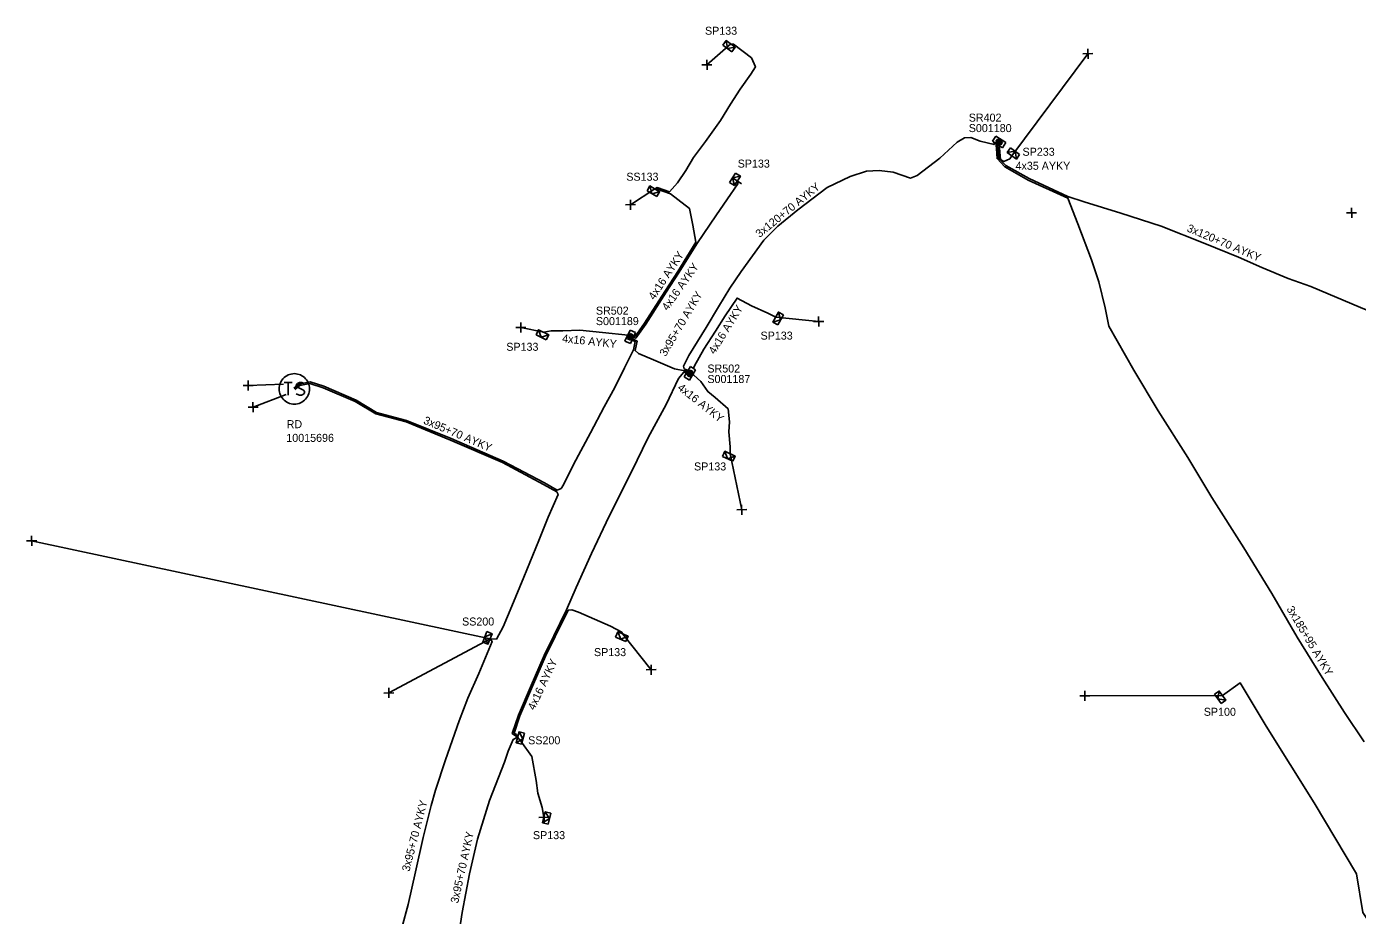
# Model space of a CAD drawing. Extents: x -762504 to -761250, y -1152974 to -1152253.
# Drawn here: x -761820.6 to -761655.3, y -1152363.5 to -1152253.1 of the extents above; entities that cross this region are included whole.
import ezdxf

# ---------------------------------------------------------------- set-up
doc = ezdxf.new("R2010")
doc.units = 0
for name, color, linetype in [('Vrstva 25', 7, 'Continuous'), ('Vrstva 26', 7, 'Continuous'), ('Vrstva 27', 7, 'Continuous'), ('Vrstva 28', 7, 'Continuous'), ('Vrstva 29', 7, 'Continuous'), ('Vrstva 30', 7, 'Continuous'), ('Vrstva 31', 7, 'Continuous'), ('Vrstva 33', 7, 'Continuous'), ('Vrstva 34', 7, 'Continuous'), ('Vrstva 5', 7, 'Continuous'), ('Vrstva 52', 7, 'Continuous'), ('Vrstva 54', 7, 'Continuous'), ('Vrstva 59', 7, 'Continuous'), ('Vrstva 6', 7, 'Continuous')]:
    doc.layers.add(name, color=color, linetype=linetype)

msp = doc.modelspace()

# ---------------------------------------------------------------- linework, layer by layer
at = {"layer": 'Vrstva 25'}
for points in [[(-761785.487, -1152298.121), (-761785.498, -1152297.924), (-761785.529, -1152297.728), (-761785.58, -1152297.537), (-761785.651, -1152297.352), (-761785.741, -1152297.177), (-761785.849, -1152297.011), (-761785.973, -1152296.857), (-761786.113, -1152296.717), (-761786.267, -1152296.593), (-761786.433, -1152296.485), (-761786.609, -1152296.395), (-761786.793, -1152296.324), (-761787.18, -1152296.242), (-761787.18, -1152296.242), (-761787.377, -1152296.231), (-761787.575, -1152296.242), (-761787.771, -1152296.273), (-761787.961, -1152296.324), (-761788.147, -1152296.395), (-761788.322, -1152296.485), (-761788.488, -1152296.593), (-761788.642, -1152296.717), (-761788.782, -1152296.857), (-761788.906, -1152297.011), (-761789.014, -1152297.177), (-761789.104, -1152297.352), (-761789.175, -1152297.537), (-761789.226, -1152297.728), (-761789.257, -1152297.924), (-761789.268, -1152298.121), (-761789.257, -1152298.319), (-761789.226, -1152298.515), (-761789.175, -1152298.705), (-761789.104, -1152298.89), (-761789.014, -1152299.066), (-761788.906, -1152299.232), (-761788.781, -1152299.386), (-761788.642, -1152299.525), (-761788.488, -1152299.65), (-761788.322, -1152299.758), (-761788.146, -1152299.848), (-761787.961, -1152299.919), (-761787.771, -1152299.97), (-761787.575, -1152300.001), (-761787.377, -1152300.012), (-761787.18, -1152300.001), (-761786.984, -1152299.97), (-761786.793, -1152299.919), (-761786.609, -1152299.848), (-761786.433, -1152299.758), (-761786.267, -1152299.65), (-761786.113, -1152299.525), (-761785.973, -1152299.386), (-761785.849, -1152299.232), (-761785.741, -1152299.066), (-761785.651, -1152298.89), (-761785.58, -1152298.705), (-761785.529, -1152298.515), (-761785.498, -1152298.319), (-761785.487, -1152298.121)], [(-761788.639, -1152297.338), (-761787.631, -1152297.338)], [(-761788.135, -1152297.338), (-761788.135, -1152298.912)], [(-761786.182, -1152297.464), (-761786.434, -1152297.338), (-761786.749, -1152297.338), (-761787.001, -1152297.464), (-761787.127, -1152297.652), (-761787.127, -1152297.716), (-761787.001, -1152297.904), (-761786.245, -1152298.282), (-761786.119, -1152298.44), (-761786.119, -1152298.598), (-761786.245, -1152298.786), (-761786.497, -1152298.912), (-761786.749, -1152298.912), (-761786.875, -1152298.85), (-761787.127, -1152298.724)]]:
    msp.add_lwpolyline(points, dxfattribs=at)
at = {"layer": 'Vrstva 28'}
for points in [[(-761700.254, -1152266.724), (-761700.663, -1152267.353)], [(-761698.996, -1152267.541), (-761700.254, -1152266.724)], [(-761700.663, -1152267.353), (-761699.405, -1152268.17)], [(-761700.035, -1152267.092), (-761700.241, -1152267.409)], [(-761700.241, -1152267.409), (-761699.617, -1152267.814)], [(-761700.021, -1152267.157), (-761700.176, -1152267.395)], [(-761700.176, -1152267.395), (-761699.631, -1152267.749)], [(-761700.007, -1152267.223), (-761700.11, -1152267.381)], [(-761700.11, -1152267.381), (-761699.645, -1152267.683)], [(-761699.994, -1152267.288), (-761700.045, -1152267.367)], [(-761700.045, -1152267.367), (-761699.659, -1152267.618)], [(-761699.411, -1152267.497), (-761700.035, -1152267.092)], [(-761699.476, -1152267.511), (-761700.021, -1152267.157)], [(-761699.542, -1152267.525), (-761700.007, -1152267.223)], [(-761699.607, -1152267.539), (-761699.994, -1152267.288)], [(-761699.668, -1152267.556), (-761699.985, -1152267.35)], [(-761699.659, -1152267.618), (-761699.607, -1152267.539)], [(-761699.645, -1152267.683), (-761699.542, -1152267.525)], [(-761699.631, -1152267.749), (-761699.476, -1152267.511)], [(-761699.617, -1152267.814), (-761699.411, -1152267.497)], [(-761699.405, -1152268.17), (-761698.996, -1152267.541)], [(-761745.68, -1152290.817), (-761746.314, -1152292.176)], [(-761745.666, -1152291.234), (-761745.981, -1152291.908)], [(-761745.644, -1152291.297), (-761745.918, -1152291.885)], [(-761745.621, -1152291.359), (-761745.855, -1152291.862)], [(-761745.598, -1152291.422), (-761745.793, -1152291.84)], [(-761745.573, -1152291.48), (-761745.732, -1152291.822)], [(-761745.707, -1152291.88), (-761745.512, -1152291.462)], [(-761745.684, -1152291.942), (-761745.449, -1152291.439)], [(-761745.001, -1152291.134), (-761745.68, -1152290.817)], [(-761745.324, -1152291.393), (-761745.666, -1152291.234)], [(-761745.661, -1152292.005), (-761745.387, -1152291.416)], [(-761745.387, -1152291.416), (-761745.644, -1152291.297)], [(-761745.638, -1152292.068), (-761745.324, -1152291.393)], [(-761745.635, -1152292.493), (-761745.001, -1152291.134)], [(-761745.449, -1152291.439), (-761745.621, -1152291.359)], [(-761745.512, -1152291.462), (-761745.598, -1152291.422)], [(-761746.314, -1152292.176), (-761745.635, -1152292.493)], [(-761745.981, -1152291.908), (-761745.638, -1152292.068)], [(-761745.918, -1152291.885), (-761745.661, -1152292.005)], [(-761745.855, -1152291.862), (-761745.684, -1152291.942)], [(-761745.793, -1152291.84), (-761745.707, -1152291.88)], [(-761738.176, -1152295.354), (-761738.948, -1152296.639)], [(-761738.948, -1152296.639), (-761738.305, -1152297.026)], [(-761738.216, -1152295.777), (-761738.6, -1152296.415)], [(-761738.6, -1152296.415), (-761738.276, -1152296.609)], [(-761738.2, -1152295.842), (-761738.535, -1152296.398)], [(-761738.535, -1152296.398), (-761738.292, -1152296.544)], [(-761738.184, -1152295.906), (-761738.47, -1152296.382)], [(-761738.47, -1152296.382), (-761738.308, -1152296.48)], [(-761738.168, -1152295.971), (-761738.405, -1152296.366)], [(-761738.405, -1152296.366), (-761738.324, -1152296.415)], [(-761738.343, -1152296.355), (-761738.149, -1152296.031)], [(-761738.324, -1152296.415), (-761738.087, -1152296.02)], [(-761738.308, -1152296.48), (-761738.022, -1152296.004)], [(-761738.305, -1152297.026), (-761737.533, -1152295.74)], [(-761738.292, -1152296.544), (-761737.957, -1152295.988)], [(-761738.276, -1152296.609), (-761737.892, -1152295.971)], [(-761737.892, -1152295.971), (-761738.216, -1152295.777)], [(-761737.957, -1152295.988), (-761738.2, -1152295.842)], [(-761738.022, -1152296.004), (-761738.184, -1152295.906)], [(-761737.533, -1152295.74), (-761738.176, -1152295.354)], [(-761738.087, -1152296.02), (-761738.168, -1152295.971)]]:
    msp.add_lwpolyline(points, dxfattribs=at)
at = {"layer": 'Vrstva 31'}
for points in [[(-761734.143, -1152255.416), (-761733.722, -1152254.857), (-761732.603, -1152255.7), (-761733.025, -1152256.259)], [(-761733.584, -1152255.838), (-761733.722, -1152254.857)], [(-761734.143, -1152255.416), (-761733.025, -1152256.259)], [(-761733.584, -1152255.838), (-761732.603, -1152255.7)], [(-761697.29, -1152269.017), (-761697.701, -1152269.583), (-761698.834, -1152268.76), (-761698.422, -1152268.194)], [(-761697.29, -1152269.017), (-761698.422, -1152268.194)], [(-761697.856, -1152268.605), (-761698.834, -1152268.76)], [(-761697.856, -1152268.605), (-761697.701, -1152269.583)], [(-761732.571, -1152271.323), (-761733.313, -1152272.51)], [(-761732.571, -1152271.323), (-761731.978, -1152271.694), (-761732.72, -1152272.881), (-761733.313, -1152272.51)], [(-761732.942, -1152271.916), (-761731.978, -1152271.694)], [(-761743.563, -1152273.518), (-761743.203, -1152272.918), (-761742.003, -1152273.639), (-761742.363, -1152274.239)], [(-761743.563, -1152273.518), (-761742.363, -1152274.239)], [(-761742.963, -1152273.879), (-761743.203, -1152272.918)], [(-761732.942, -1152271.916), (-761732.72, -1152272.881)], [(-761742.963, -1152273.879), (-761742.003, -1152273.639)], [(-761727.318, -1152290.154), (-761727.93, -1152289.815), (-761727.252, -1152288.59), (-761726.639, -1152288.93)], [(-761726.979, -1152289.542), (-761727.93, -1152289.815)], [(-761727.318, -1152290.154), (-761726.639, -1152288.93)], [(-761726.979, -1152289.542), (-761727.252, -1152288.59)], [(-761757.339, -1152291.411), (-761757.032, -1152290.782), (-761755.774, -1152291.396), (-761756.081, -1152292.025)], [(-761757.339, -1152291.411), (-761756.081, -1152292.025)], [(-761756.71, -1152291.718), (-761757.032, -1152290.782)], [(-761756.71, -1152291.718), (-761755.774, -1152291.396)], [(-761734.193, -1152306.508), (-761733.897, -1152305.873), (-761732.628, -1152306.465), (-761732.924, -1152307.099)], [(-761734.193, -1152306.508), (-761732.924, -1152307.099)], [(-761733.559, -1152306.804), (-761733.897, -1152305.873)], [(-761733.559, -1152306.804), (-761732.628, -1152306.465)], [(-761763.456, -1152328.266), (-761763.981, -1152329.564)], [(-761763.456, -1152328.266), (-761762.807, -1152328.528), (-761763.331, -1152329.826), (-761763.981, -1152329.564)], [(-761763.718, -1152328.915), (-761762.807, -1152328.528)], [(-761763.718, -1152328.915), (-761763.331, -1152329.826)], [(-761747.481, -1152328.94), (-761747.207, -1152328.296), (-761745.918, -1152328.843), (-761746.192, -1152329.487)], [(-761747.481, -1152328.94), (-761746.192, -1152329.487)], [(-761746.836, -1152329.214), (-761747.207, -1152328.296)], [(-761746.836, -1152329.214), (-761745.918, -1152328.843)], [(-761673.077, -1152336.046), (-761672.503, -1152335.644), (-761671.7, -1152336.791), (-761672.274, -1152337.193)], [(-761673.077, -1152336.046), (-761672.274, -1152337.193)], [(-761672.675, -1152336.619), (-761672.503, -1152335.644)], [(-761672.675, -1152336.619), (-761671.7, -1152336.791)], [(-761759.155, -1152342.24), (-761759.832, -1152342.059), (-761759.469, -1152340.707), (-761758.793, -1152340.888)], [(-761758.974, -1152341.564), (-761759.469, -1152340.707)], [(-761759.155, -1152342.24), (-761758.793, -1152340.888)], [(-761758.974, -1152341.564), (-761759.832, -1152342.059)], [(-761755.86, -1152352.171), (-761756.54, -1152352.002), (-761756.201, -1152350.644), (-761755.522, -1152350.813)], [(-761755.691, -1152351.492), (-761756.201, -1152350.644)], [(-761755.86, -1152352.171), (-761755.522, -1152350.813)], [(-761755.691, -1152351.492), (-761756.54, -1152352.002)]]:
    msp.add_lwpolyline(points, dxfattribs=at)
at = {"layer": 'Vrstva 34'}
for points in [[(-761689.435, -1152256.511), (-761688.185, -1152256.489)], [(-761688.799, -1152257.125), (-761688.821, -1152255.875)], [(-761736.755, -1152257.891), (-761735.505, -1152257.869)], [(-761736.119, -1152258.505), (-761736.141, -1152257.255)], [(-761732.708, -1152272.802), (-761731.991, -1152271.778)], [(-761731.838, -1152272.649), (-761732.862, -1152271.932)], [(-761745.619, -1152275.875), (-761745.641, -1152274.625)], [(-761746.255, -1152275.261), (-761745.005, -1152275.239)], [(-761656.685, -1152276.261), (-761655.435, -1152276.239)], [(-761656.049, -1152276.875), (-761656.071, -1152275.625)], [(-761759.239, -1152291.125), (-761759.261, -1152289.875)], [(-761722.875, -1152289.761), (-761721.625, -1152289.739)], [(-761722.239, -1152290.375), (-761722.261, -1152289.125)], [(-761759.875, -1152290.511), (-761758.625, -1152290.489)], [(-761793.725, -1152297.711), (-761792.475, -1152297.689)], [(-761793.089, -1152298.325), (-761793.111, -1152297.075)], [(-761792.489, -1152301.025), (-761792.511, -1152299.775)], [(-761793.125, -1152300.411), (-761791.875, -1152300.389)], [(-761732.435, -1152313.141), (-761731.185, -1152313.119)], [(-761731.799, -1152313.755), (-761731.821, -1152312.505)], [(-761819.989, -1152317.625), (-761820.011, -1152316.375)], [(-761820.625, -1152317.011), (-761819.375, -1152316.989)], [(-761743.685, -1152333.011), (-761742.435, -1152332.989)], [(-761743.049, -1152333.625), (-761743.071, -1152332.375)], [(-761776.255, -1152335.891), (-761775.005, -1152335.869)], [(-761775.619, -1152336.505), (-761775.641, -1152335.255)], [(-761689.815, -1152336.261), (-761688.565, -1152336.239)], [(-761689.179, -1152336.875), (-761689.201, -1152335.625)], [(-761756.359, -1152351.965), (-761756.381, -1152350.715)], [(-761756.995, -1152351.351), (-761755.745, -1152351.329)]]:
    msp.add_lwpolyline(points, dxfattribs=at)
at = {"layer": 'Vrstva 5'}
for points in [[(-761745.19, -1152291.54), (-761745.05, -1152291.6), (-761743.89, -1152289.98), (-761741.34, -1152286.02), (-761739.75, -1152283.53), (-761737.49, -1152279.9), (-761737.87, -1152277.79), (-761738.31, -1152275.71), (-761739.75, -1152274.62), (-761740.65, -1152273.88), (-761742.32, -1152273.33), (-761742.6, -1152273.28), (-761742.3, -1152273.13), (-761740.79, -1152273.63), (-761739.79, -1152272.53), (-761738.75, -1152271.01), (-761737.78, -1152269.39), (-761736.29, -1152267.41), (-761734.44, -1152264.81), (-761733.22, -1152262.76), (-761732.02, -1152260.89), (-761730.68, -1152259.02), (-761730.1, -1152258.11), (-761730.59, -1152257.01), (-761732.81, -1152255.3), (-761733.16, -1152255.28)], [(-761700.49, -1152267.45), (-761700.47, -1152267.79), (-761702.2, -1152267.36), (-761703.36, -1152266.92), (-761704.13, -1152266.93), (-761705.05, -1152267.48), (-761707.19, -1152269.46), (-761710, -1152271.63), (-761710.83, -1152271.97), (-761713, -1152271.21), (-761714.72, -1152270.98), (-761716.3, -1152271.09), (-761718.33, -1152271.73), (-761721.19, -1152273.11), (-761724.84, -1152275.9), (-761727.33, -1152277.93), (-761729.06, -1152279.66), (-761731.86, -1152283.56), (-761733.3, -1152285.61), (-761734.68, -1152287.93), (-761736.24, -1152290.51), (-761738.37, -1152293.96), (-761739.06, -1152295.29), (-761738.95, -1152295.64), (-761738.45, -1152295.83)], [(-761654.51, -1152341.94), (-761656.95, -1152338.33), (-761659.7, -1152333.97), (-761662.81, -1152328.96), (-761665.98, -1152323.54), (-761669.44, -1152317.85), (-761673.42, -1152311.6), (-761676.42, -1152306.66), (-761680.09, -1152300.84), (-761683.11, -1152295.81), (-761686.2, -1152290.34), (-761686.68, -1152288.06), (-761687.44, -1152284.83), (-761688.36, -1152282.1), (-761690.08, -1152277.64), (-761691.29, -1152274.45), (-761696.22, -1152272.19), (-761699.11, -1152270.55), (-761700.09, -1152269.52), (-761700.18, -1152268.26), (-761700.25, -1152267.62)], [(-761648.6, -1152289.99), (-761648.69, -1152290.32), (-761649.19, -1152290.28), (-761651.67, -1152289.32), (-761654.97, -1152288.01), (-761661.13, -1152285.42), (-761663.93, -1152284.42), (-761667.23, -1152283.04), (-761670.12, -1152281.75), (-761674.31, -1152280.06), (-761679.7, -1152277.9), (-761684.72, -1152276.28), (-761689.26, -1152274.88), (-761691.3, -1152274.22), (-761696.12, -1152272.01), (-761698.99, -1152270.39), (-761699.89, -1152269.51), (-761699.98, -1152268.24), (-761700.03, -1152267.76)], [(-761699.81, -1152267.9), (-761699.78, -1152268.22), (-761699.68, -1152269.63), (-761699.24, -1152269.87), (-761698.52, -1152269.57), (-761698.27, -1152269.17)], [(-761745.28, -1152291.72), (-761744.97, -1152291.84), (-761743.73, -1152290.1), (-761741.18, -1152286.12), (-761739.58, -1152283.63), (-761737.38, -1152280.1), (-761734.95, -1152276.5), (-761733.21, -1152273.98), (-761732.29, -1152272.64), (-761732.35, -1152272.29)], [(-761737.85, -1152295.65), (-761737.66, -1152295.25), (-761736.53, -1152293.17), (-761735.06, -1152290.94), (-761733.87, -1152289.03), (-761732.39, -1152286.85), (-761730.61, -1152287.82), (-761728.57, -1152288.73), (-761727.59, -1152289.2)], [(-761756.4, -1152291.09), (-761755.48, -1152290.92), (-761754.03, -1152290.92), (-761751.93, -1152290.82), (-761749.1, -1152291.13), (-761745.91, -1152291.47)], [(-761745.45, -1152292.08), (-761745.03, -1152292.25), (-761745.25, -1152293.28), (-761746.35, -1152295.5), (-761747.55, -1152297.93), (-761748.91, -1152300.37), (-761750.58, -1152303.58), (-761752.7, -1152307.52), (-761753.95, -1152310.05), (-761754.25, -1152310.49), (-761754.74, -1152310.71), (-761756.32, -1152309.8), (-761761.42, -1152307.1), (-761767.91, -1152304.29), (-761773.44, -1152302.03), (-761777.18, -1152301.06), (-761779.7, -1152299.52), (-761783.72, -1152297.8), (-761785.42, -1152297.25), (-761786.78, -1152297.52), (-761787.43, -1152298.04)], [(-761738.56, -1152296), (-761738.88, -1152295.88), (-761740.15, -1152295.62), (-761742.78, -1152294.5), (-761744.63, -1152293.73), (-761745.06, -1152293.37), (-761744.81, -1152292.19), (-761745.36, -1152291.9)], [(-761767.25, -1152367.79), (-761766.52, -1152363.16), (-761765.63, -1152358.34), (-761764.62, -1152354.03), (-761763.12, -1152349.26), (-761761.26, -1152344.49), (-761760.81, -1152343.13), (-761760.18, -1152341.66), (-761759.65, -1152341.38), (-761760.31, -1152340.94), (-761759.54, -1152338.65), (-761757.97, -1152334.97), (-761756.35, -1152331.25), (-761755.15, -1152328.79), (-761753.56, -1152325.58), (-761752.36, -1152322.78), (-761750.46, -1152318.55), (-761748.26, -1152313.93), (-761745.48, -1152308.41), (-761743.41, -1152304.17), (-761741.18, -1152300.05), (-761739.64, -1152296.84), (-761739.01, -1152296.04), (-761738.67, -1152296.17)], [(-761733.26, -1152306.17), (-761733.25, -1152305.33), (-761733.41, -1152303.46), (-761733.31, -1152302.2), (-761733.5, -1152300.61), (-761735.12, -1152299.2), (-761736.02, -1152298.46), (-761736.9, -1152297.2), (-761737.74, -1152296.4), (-761737.95, -1152296.3)], [(-761787.31, -1152298.2), (-761786.7, -1152297.7), (-761785.44, -1152297.45), (-761783.79, -1152297.98), (-761779.8, -1152299.7), (-761777.26, -1152301.24), (-761773.5, -1152302.23), (-761767.99, -1152304.47), (-761761.5, -1152307.28), (-761756.42, -1152309.98), (-761754.77, -1152310.92), (-761754.61, -1152311.24), (-761755.85, -1152314.06), (-761756.99, -1152316.96), (-761758.87, -1152321.49), (-761760.35, -1152325.12), (-761761.44, -1152327.69), (-761762.28, -1152329.19), (-761763.07, -1152329.18), (-761762.81, -1152329.5), (-761764.45, -1152333.47), (-761765.81, -1152336.55), (-761766.9, -1152339.35), (-761768.61, -1152344.21), (-761769.86, -1152347.97), (-761770.39, -1152349.87), (-761771.37, -1152353.83), (-761772.32, -1152358.08), (-761773.23, -1152362.16), (-761774.04, -1152365.05)], [(-761634.35, -1152376.55), (-761634.84, -1152376.97), (-761632.99, -1152380.85), (-761633.54, -1152381.11), (-761638.35, -1152386.44), (-761640.07, -1152387.6), (-761640.77, -1152384.25), (-761646.56, -1152375.28), (-761654.67, -1152363.13), (-761655.44, -1152358.33), (-761660.7, -1152349.53), (-761666.67, -1152339.99), (-761669.92, -1152334.61), (-761672.1, -1152336.22)]]:
    msp.add_lwpolyline(points, dxfattribs=at)
at = {"layer": 'Vrstva 52'}
for points in [[(-761759.65, -1152341.38), (-761759.8, -1152341.05), (-761760.07, -1152340.88), (-761759.36, -1152338.72), (-761757.79, -1152335.05), (-761756.17, -1152331.33), (-761754.97, -1152328.87), (-761753.35, -1152325.61), (-761752.89, -1152325.57), (-761752.06, -1152325.85), (-761748.1, -1152327.57), (-761746.71, -1152328.32), (-761746.56, -1152328.57)], [(-761759.65, -1152341.38), (-761759.23, -1152341.87), (-761757.88, -1152343.77), (-761757.35, -1152346.76), (-761757.15, -1152348.34), (-761756.58, -1152350.11), (-761756.37, -1152351.32)]]:
    msp.add_lwpolyline(points, dxfattribs=at)
at = {"layer": 'Vrstva 59'}
for points in [[(-761733.16, -1152255.28), (-761736.13, -1152257.88)], [(-761698.27, -1152269.17), (-761688.81, -1152256.5)], [(-761742.6, -1152273.28), (-761745.63, -1152275.25)], [(-761727.59, -1152289.2), (-761722.25, -1152289.75)], [(-761756.4, -1152291.09), (-761759.25, -1152290.5)], [(-761788.7, -1152297.53), (-761793.1, -1152297.7)], [(-761788.39, -1152298.83), (-761792.5, -1152300.4)], [(-761733.26, -1152306.17), (-761731.81, -1152313.13)], [(-761763.07, -1152329.18), (-761820, -1152317)], [(-761763.07, -1152329.18), (-761775.63, -1152335.88)], [(-761746.56, -1152328.57), (-761743.06, -1152333)], [(-761672.1, -1152336.22), (-761689.19, -1152336.25)]]:
    msp.add_lwpolyline(points, dxfattribs=at)

# ---------------------------------------------------------------- texts
at = {"layer": 'Vrstva 26'}
msp.add_text('10015696', height=0.9943, dxfattribs=at).set_placement((-761788.37, -1152304.7))
at = {"layer": 'Vrstva 27'}
msp.add_text('RD', height=0.9943, dxfattribs=at).set_placement((-761788.33, -1152303))
at = {"layer": 'Vrstva 29'}
for s, p in [('S001180', (-761703.61, -1152266.23)), ('S001189', (-761749.92, -1152290.2)), ('S001187', (-761736.07, -1152297.39))]:
    msp.add_text(s, height=0.9943, dxfattribs=at).set_placement(p)
at = {"layer": 'Vrstva 30'}
for s, p in [('SR402', (-761703.61, -1152264.93)), ('SR502', (-761749.92, -1152288.9)), ('SR502', (-761736.07, -1152296.09))]:
    msp.add_text(s, height=0.9943, dxfattribs=at).set_placement(p)
at = {"layer": 'Vrstva 33'}
for s, p in [('SP133', (-761736.37, -1152254.14)), ('SP233', (-761696.93, -1152269.17)), ('SP133', (-761732.31, -1152270.64)), ('SS133', (-761746.14, -1152272.27)), ('SP133', (-761729.47, -1152292)), ('SP133', (-761761.05, -1152293.39)), ('SP133', (-761737.73, -1152308.25)), ('SS200', (-761766.54, -1152327.51)), ('SP133', (-761750.16, -1152331.31)), ('SP100', (-761674.42, -1152338.72)), ('SS200', (-761758.33, -1152342.26)), ('SP133', (-761757.74, -1152354.04))]:
    msp.add_text(s, height=0.9943, dxfattribs=at).set_placement(p)
at = {"layer": 'Vrstva 54'}
msp.add_text('4x16 AYKY', height=0.9943, rotation=64.96542, dxfattribs=at).set_placement((-761757.55, -1152338.1))
at = {"layer": 'Vrstva 6'}
msp.add_text('4x35 AYKY', height=0.9943, dxfattribs=at).set_placement((-761697.8, -1152270.91))
for s, height, rotation, p in [('3x120+70 AYKY', 0.99429, 39.14801, (-761729.59, -1152279.39)), ('3x120+70 AYKY', 0.99429, 337.15858, (-761676.6, -1152278.53)), ('4x16 AYKY', 0.9943, 56.72511, (-761742.66, -1152287.15)), ('4x16 AYKY', 0.9943, 54.60903, (-761741.02, -1152288.49)), ('3x95+70 AYKY', 0.99429, 59.34933, (-761741.25, -1152294.17)), ('4x16 AYKY', 0.9943, 58.35098, (-761735.17, -1152293.9)), ('4x16 AYKY', 0.9943, 353.82983, (-761754.15, -1152292.32)), ('4x16 AYKY', 0.9943, 321.73857, (-761739.87, -1152298.14)), ('3x95+70 AYKY', 0.99428, 336.90087, (-761771.43, -1152302.39)), ('3x185+95 AYKY', 0.99429, 300.85128, (-761664.18, -1152325.45)), ('3x95+70 AYKY', 0.99429, 75.60105, (-761773.08, -1152358.13)), ('3x95+70 AYKY', 0.99429, 77.51191, (-761767.03, -1152362.07))]:
    msp.add_text(s, height=height, rotation=rotation, dxfattribs=at).set_placement(p)

doc.saveas('drawing.dxf')
